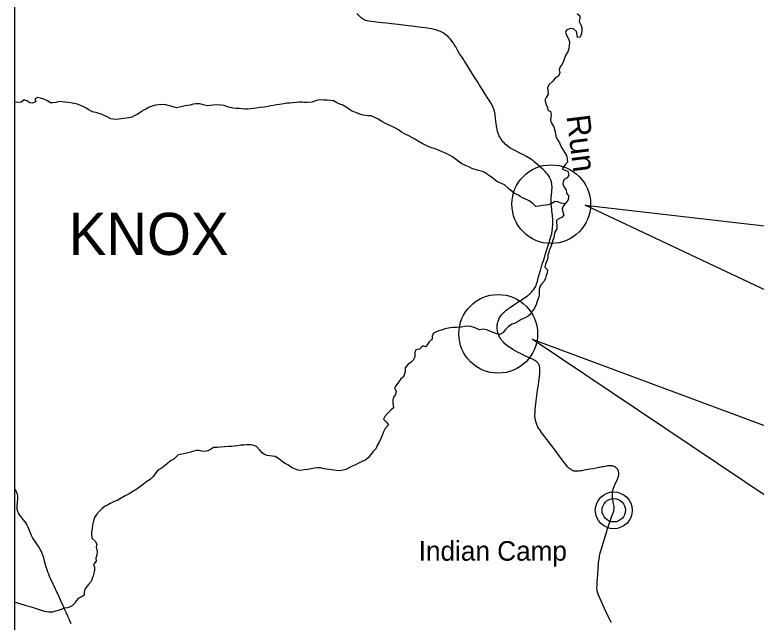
# Model space of a CAD drawing. Extents: x -29.6 to 34, y 0 to 22.
# Drawn here: x -29.583 to -26.775, y 7.101 to 9.402 of the extents above; entities that cross this region are included whole.
import ezdxf

# ---------------------------------------------------------------- set-up
doc = ezdxf.new("R2010")
doc.units = 0
for name, color, linetype in [('BR_P_Gen_Text', 7, 'Continuous'), ('Default', 7, 'Continuous'), ('GM_X_Minor_River', 7, 'Continuous'), ('GM_X_Minor_River_Text', 7, 'Continuous'), ('GM_X_State_Route', 7, 'Continuous'), ('GM_X_Township_Text', 7, 'Continuous'), ('GM_X_Unincorporated', 7, 'Continuous'), ('GM_X_Unincorporated_Location', 7, 'Continuous'), ('GM_X_Unincorporated_Text', 7, 'Continuous'), ('SH_Text', 7, 'Continuous')]:
    doc.layers.add(name, color=color, linetype=linetype)

msp = doc.modelspace()

# ---------------------------------------------------------------- linework, layer by layer
at = {"layer": 'BR_P_Gen_Text'}
for points in [[(-26.5791, 8.5837), (-26.5791, 8.2835), (-27.4233, 8.6813)], [(-26.6185, 7.7998), (-26.6185, 7.4995), (-27.6231, 8.1727)]]:
    msp.add_lwpolyline(points, close=True, dxfattribs=at)
at = {"layer": 'Default'}
for centre in [(-27.5513, 8.6845), (-27.7521, 8.1933)]:
    msp.add_circle(centre, 0.149, dxfattribs=at)
at = {"layer": 'GM_X_Minor_River'}
for points in [[(-27.4532, 9.4073), (-27.4428, 9.3986), (-27.4435, 9.3886), (-27.4448, 9.3769), (-27.4393, 9.3638), (-27.4353, 9.3539), (-27.4349, 9.3404), (-27.4376, 9.3268), (-27.4417, 9.3172), (-27.4513, 9.3157), (-27.4528, 9.3249), (-27.4554, 9.3391), (-27.4672, 9.3486), (-27.4796, 9.3495), (-27.4934, 9.3441), (-27.4976, 9.3344), (-27.4936, 9.3249), (-27.4853, 9.3104), (-27.482, 9.299), (-27.483, 9.2848), (-27.4846, 9.2742), (-27.4884, 9.262), (-27.4958, 9.2499), (-27.5006, 9.2381), (-27.5044, 9.2264), (-27.51, 9.2149), (-27.517, 9.2042), (-27.5218, 9.1931), (-27.5186, 9.1839), (-27.5241, 9.17), (-27.5358, 9.1621), (-27.5452, 9.151), (-27.5597, 9.1384), (-27.5659, 9.1263), (-27.5637, 9.1146), (-27.5625, 9.1011), (-27.5699, 9.0886), (-27.5754, 9.0779), (-27.5703, 9.0623), (-27.566, 9.0513), (-27.5637, 9.041), (-27.5541, 9.0361), (-27.5512, 9.0255), (-27.5532, 9.0123), (-27.5541, 9.001), (-27.5502, 8.9914), (-27.5415, 8.978), (-27.5371, 8.9635), (-27.5356, 8.9511), (-27.5323, 8.9369), (-27.5265, 8.9273), (-27.5197, 8.9164), (-27.5124, 8.8994), (-27.5056, 8.8885), (-27.4991, 8.8789), (-27.494, 8.8687), (-27.4911, 8.8563), (-27.4899, 8.8438), (-27.4997, 8.8317), (-27.5099, 8.8188), (-27.5003, 8.8139), (-27.4889, 8.809), (-27.4845, 8.7942), (-27.4915, 8.7848), (-27.501, 8.7798), (-27.5066, 8.7701), (-27.5069, 8.7609), (-27.5018, 8.7485), (-27.4953, 8.7393), (-27.4938, 8.7262), (-27.4862, 8.7167), (-27.4862, 8.7074), (-27.4879, 8.6985), (-27.4977, 8.6881), (-27.5075, 8.6745), (-27.5103, 8.6653), (-27.5077, 8.6543), (-27.5033, 8.644), (-27.5096, 8.6347), (-27.5227, 8.6289), (-27.5319, 8.6242), (-27.5318, 8.6153), (-27.5296, 8.6054), (-27.5298, 8.5912), (-27.5371, 8.5783), (-27.5406, 8.5669), (-27.5415, 8.5573), (-27.5457, 8.548), (-27.5495, 8.5342), (-27.5529, 8.5235)], [(-28.7119, 9.0443), (-28.7236, 9.046), (-28.7339, 9.0466), (-28.7446, 9.0469), (-28.7559, 9.0482), (-28.7694, 9.0512), (-28.7819, 9.0547), (-28.7908, 9.0581), (-28.8032, 9.0598), (-28.8195, 9.0614), (-28.832, 9.0602), (-28.8433, 9.0587), (-28.8529, 9.0575), (-28.8649, 9.0602), (-28.8738, 9.0626), (-28.8834, 9.0643), (-28.8976, 9.0642), (-28.9072, 9.063), (-28.9192, 9.0593), (-28.9291, 9.0581), (-28.9384, 9.057), (-28.9497, 9.0551), (-28.9592, 9.0522), (-28.9709, 9.0496), (-28.9798, 9.0516), (-28.9919, 9.0554), (-29.0026, 9.0588), (-29.0118, 9.0605), (-29.0253, 9.0618), (-29.0384, 9.0609), (-29.0508, 9.059), (-29.0625, 9.0564), (-29.0742, 9.0517), (-29.0869, 9.0445), (-29.0968, 9.0394), (-29.1084, 9.0318), (-29.1179, 9.026), (-29.1307, 9.0195), (-29.1398, 9.0144), (-29.1515, 9.0115), (-29.1799, 9.0076), (-29.1894, 9.0061), (-29.2008, 9.0053), (-29.2111, 9.0062), (-29.2199, 9.0083), (-29.2338, 9.0149), (-29.2449, 9.0201), (-29.2559, 9.025), (-29.2652, 9.0284), (-29.2755, 9.0312), (-29.2844, 9.0336), (-29.2936, 9.0374), (-29.3026, 9.0419), (-29.3133, 9.0478), (-29.325, 9.0541), (-29.3339, 9.0586), (-29.3457, 9.0631), (-29.3592, 9.0662), (-29.3723, 9.0685), (-29.3816, 9.0699), (-29.3933, 9.0715), (-29.4057, 9.0725), (-29.4149, 9.0731), (-29.4273, 9.0698), (-29.4387, 9.0679), (-29.4475, 9.0688), (-29.4618, 9.0769), (-29.4736, 9.0817), (-29.4857, 9.0859), (-29.497, 9.0882), (-29.5069, 9.0832), (-29.5043, 9.0732), (-29.516, 9.0671), (-29.527, 9.068), (-29.5384, 9.0757), (-29.548, 9.0802), (-29.5593, 9.0713), (-29.5721, 9.0701), (-29.5827, 9.071), (-29.5833, 9.0715)], [(-27.4996, 8.6855), (-27.5066, 8.6873), (-27.5154, 8.6883), (-27.5268, 8.6928), (-27.5368, 8.6942), (-27.5516, 8.6862), (-27.5629, 8.6818), (-27.5732, 8.6807), (-27.5849, 8.6791), (-27.5969, 8.6772), (-27.61, 8.6753), (-27.6219, 8.6887), (-27.6354, 8.6971), (-27.6508, 8.7044), (-27.6597, 8.709), (-27.6686, 8.7142), (-27.6775, 8.7198), (-27.6903, 8.7254), (-27.6996, 8.7331), (-27.7136, 8.744), (-27.7282, 8.7577), (-27.7393, 8.7632), (-27.7489, 8.7667), (-27.7578, 8.7709), (-27.7725, 8.7832), (-27.7814, 8.7898), (-27.796, 8.7996), (-27.8057, 8.8056), (-27.8153, 8.8098), (-27.8263, 8.8125), (-27.8395, 8.8159), (-27.8491, 8.8187), (-27.864, 8.8256), (-27.8765, 8.8315), (-27.8893, 8.8371), (-27.8993, 8.8434), (-27.9101, 8.8522), (-27.9251, 8.8638), (-27.9397, 8.8718), (-27.9515, 8.8781), (-27.9639, 8.8833), (-27.9782, 8.8892), (-27.9945, 8.8954), (-28.0045, 8.8985), (-28.0134, 8.9023), (-28.0227, 8.9058), (-28.0398, 8.9142), (-28.0548, 8.9229), (-28.0683, 8.9313), (-28.0911, 8.9439), (-28.105, 8.9501), (-28.1179, 8.9571), (-28.1304, 8.9659), (-28.1407, 8.9722), (-28.1518, 8.9774), (-28.165, 8.9836), (-28.1785, 8.9899), (-28.1931, 8.9983), (-28.2074, 9.0063), (-28.2216, 9.0136), (-28.233, 9.0192), (-28.2455, 9.0195), (-28.2639, 9.0214), (-28.2764, 9.0255), (-28.2853, 9.0287), (-28.2988, 9.0342), (-28.3084, 9.0387), (-28.3195, 9.0457), (-28.3284, 9.052), (-28.3406, 9.059), (-28.3523, 9.0635), (-28.363, 9.0688), (-28.3755, 9.0757), (-28.3879, 9.0774), (-28.4003, 9.078), (-28.4135, 9.0782), (-28.4227, 9.0792), (-28.4351, 9.0783), (-28.4475, 9.0747), (-28.4574, 9.0714), (-28.4755, 9.0694), (-28.4854, 9.0697), (-28.495, 9.0706), (-28.506, 9.0709), (-28.5156, 9.0697), (-28.5297, 9.0678), (-28.5418, 9.0677), (-28.5514, 9.0669), (-28.5648, 9.065), (-28.5801, 9.062), (-28.5921, 9.0605), (-28.6031, 9.0586), (-28.613, 9.0567), (-28.6233, 9.0545), (-28.6378, 9.0525), (-28.6545, 9.0506), (-28.6686, 9.0483), (-28.6786, 9.0468), (-28.6892, 9.0456), (-28.7023, 9.0444), (-28.7119, 9.0443)], [(-27.5529, 8.5235), (-27.5582, 8.5124), (-27.5609, 8.5031), (-27.5637, 8.4917), (-27.5646, 8.48), (-27.5677, 8.4697), (-27.5733, 8.4579), (-27.5753, 8.4465), (-27.5649, 8.4352), (-27.5669, 8.4238), (-27.5704, 8.4149), (-27.5731, 8.4046), (-27.5784, 8.3935), (-27.5885, 8.3813), (-27.5945, 8.3721), (-27.5965, 8.3617), (-27.5964, 8.3497), (-27.5974, 8.3404), (-27.5998, 8.3294), (-27.6053, 8.3137), (-27.6088, 8.3044), (-27.6147, 8.2905), (-27.6224, 8.2801), (-27.629, 8.2694), (-27.6382, 8.2604), (-27.6502, 8.2546), (-27.6657, 8.2481), (-27.6766, 8.2405), (-27.6883, 8.2336), (-27.6993, 8.2296), (-27.713, 8.2217), (-27.7246, 8.2095), (-27.7341, 8.1966), (-27.7461, 8.1915), (-27.7568, 8.1939), (-27.7674, 8.197), (-27.7774, 8.2011), (-27.7867, 8.2053), (-27.7963, 8.2084), (-27.808, 8.2112), (-27.8229, 8.2082), (-27.8375, 8.2148), (-27.8464, 8.2186), (-27.8564, 8.2217), (-27.8702, 8.2223), (-27.8801, 8.2208), (-27.8915, 8.2182), (-27.9103, 8.218), (-27.923, 8.2171), (-27.934, 8.2156), (-27.9471, 8.213), (-27.9563, 8.2108), (-27.9669, 8.2078), (-27.9768, 8.2045), (-27.9864, 8.2009), (-27.997, 8.1962), (-28.0022, 8.1847), (-28.0021, 8.173), (-28.0137, 8.1633), (-28.0259, 8.144), (-28.0373, 8.1482), (-28.0507, 8.1356), (-28.0638, 8.1323), (-28.0676, 8.1226), (-28.0682, 8.1066), (-28.0748, 8.0938), (-28.0836, 8.0848), (-28.0938, 8.0783), (-28.104, 8.0651), (-28.105, 8.0551), (-28.1059, 8.0459), (-28.1111, 8.0309), (-28.1206, 8.0226), (-28.1301, 8.0097), (-28.1399, 7.9965), (-28.1451, 7.9872), (-28.1386, 7.9766), (-28.1417, 7.9641), (-28.1484, 7.9541), (-28.1515, 7.942), (-28.1517, 7.9321), (-28.1502, 7.9228), (-28.1487, 7.9129), (-28.1589, 7.9039), (-28.1719, 7.8921), (-28.1818, 7.8799), (-28.1866, 7.8706), (-28.1752, 7.8583), (-28.1676, 7.8491), (-28.1803, 7.8344), (-28.1862, 7.8223), (-28.1903, 7.8116), (-28.1956, 7.7998), (-28.2036, 7.7827), (-28.2102, 7.7698), (-28.2157, 7.7573), (-28.2256, 7.748), (-28.2351, 7.7365), (-28.2438, 7.7251), (-28.2533, 7.7165), (-28.2671, 7.7103)], [(-28.2671, 7.7103), (-28.2767, 7.7063), (-28.2957, 7.6965), (-28.3081, 7.6903), (-28.319, 7.6842), (-28.3289, 7.6795), (-28.3399, 7.6765), (-28.3523, 7.6743), (-28.3654, 7.6752), (-28.3747, 7.6765), (-28.3835, 7.6779), (-28.3924, 7.6792), (-28.4024, 7.6802), (-28.4116, 7.6822), (-28.4251, 7.6856), (-28.4351, 7.6862), (-28.4478, 7.6843), (-28.4602, 7.6821), (-28.473, 7.6795), (-28.4871, 7.6779), (-28.501, 7.6763), (-28.5112, 7.6769), (-28.5234, 7.6822), (-28.5348, 7.6874), (-28.5465, 7.6958), (-28.5587, 7.7028), (-28.5687, 7.7091), (-28.5847, 7.7217), (-28.5969, 7.7283), (-28.6079, 7.7303), (-28.6178, 7.731), (-28.6274, 7.733), (-28.6377, 7.7364), (-28.6467, 7.7428), (-28.6553, 7.7533), (-28.6682, 7.7663), (-28.6778, 7.7702), (-28.6885, 7.7725), (-28.7048, 7.7727), (-28.7151, 7.7719), (-28.7278, 7.7711), (-28.7402, 7.7692), (-28.7519, 7.7673), (-28.7611, 7.7665), (-28.7739, 7.766), (-28.7888, 7.7651), (-28.8058, 7.7639), (-28.8168, 7.7631), (-28.8306, 7.7626), (-28.8416, 7.7554), (-28.8522, 7.7499), (-28.8628, 7.7473), (-28.8763, 7.7493), (-28.8862, 7.7517), (-28.8954, 7.7509), (-28.9054, 7.7487), (-28.9163, 7.7454), (-28.9312, 7.7417), (-28.9429, 7.7394), (-28.9563, 7.7361), (-28.9645, 7.7348)], [(-28.9645, 7.7348), (-28.9705, 7.7292), (-28.981, 7.7184), (-28.9905, 7.7134), (-29.0032, 7.7036), (-29.0131, 7.6954), (-29.025, 7.6864), (-29.036, 7.6799), (-29.0451, 7.6719), (-29.0518, 7.663), (-29.0602, 7.6515), (-29.0711, 7.6418), (-29.0831, 7.6335), (-29.0958, 7.6238), (-29.1215, 7.6044), (-29.1356, 7.5957), (-29.1497, 7.5874), (-29.1649, 7.5794), (-29.1801, 7.5707), (-29.1928, 7.5638), (-29.209, 7.5573), (-29.2221, 7.5508), (-29.232, 7.545), (-29.2412, 7.5403), (-29.2528, 7.532), (-29.264, 7.5208), (-29.2742, 7.5087), (-29.2809, 7.4979), (-29.2857, 7.4847), (-29.2891, 7.4698), (-29.2907, 7.4548), (-29.2924, 7.4413), (-29.2927, 7.4321), (-29.2901, 7.4186), (-29.279, 7.4081), (-29.2732, 7.3964), (-29.2752, 7.3857), (-29.2711, 7.3687), (-29.2732, 7.3562), (-29.277, 7.3441), (-29.2747, 7.3328), (-29.2852, 7.3195), (-29.2812, 7.3092), (-29.2811, 7.2986), (-29.2842, 7.2868), (-29.2863, 7.2772), (-29.2908, 7.2669), (-29.2946, 7.2555), (-29.3044, 7.2436), (-29.3184, 7.2268), (-29.3201, 7.215), (-29.3207, 7.203), (-29.332, 7.1964), (-29.3426, 7.1924), (-29.3503, 7.182), (-29.3555, 7.1731), (-29.3643, 7.1638), (-29.3742, 7.1591), (-29.3838, 7.1558), (-29.3965, 7.1539), (-29.4075, 7.1498), (-29.4191, 7.1455), (-29.4298, 7.1425), (-29.4407, 7.1392), (-29.4563, 7.1391), (-29.4706, 7.1421), (-29.494, 7.1497), (-29.5093, 7.1538), (-29.5253, 7.1593), (-29.5399, 7.1627), (-29.5517, 7.1665), (-29.5638, 7.1703), (-29.5762, 7.1741), (-29.5833, 7.1754)]]:
    msp.add_lwpolyline(points, dxfattribs=at)
at = {"layer": 'GM_X_State_Route'}
for points in [[(-27.7557, 8.2285), (-27.7554, 8.2306), (-27.7547, 8.2339), (-27.754, 8.2366), (-27.7526, 8.2409), (-27.7503, 8.2473), (-27.7492, 8.25), (-27.747, 8.2544), (-27.7458, 8.2566), (-27.7433, 8.2604), (-27.7419, 8.2622), (-27.7382, 8.2671), (-27.7348, 8.2708), (-27.7333, 8.2724), (-27.7295, 8.276), (-27.7237, 8.2812), (-27.7166, 8.2867), (-27.706, 8.2939), (-27.6929, 8.3027), (-27.6775, 8.3129), (-27.665, 8.3213), (-27.6549, 8.3282), (-27.643, 8.3366), (-27.6375, 8.3408), (-27.6335, 8.3441), (-27.6296, 8.3476), (-27.6263, 8.3507), (-27.6243, 8.3527), (-27.6216, 8.3557), (-27.6184, 8.3598), (-27.6156, 8.3636), (-27.6133, 8.3673), (-27.6111, 8.3716), (-27.6088, 8.3768), (-27.6067, 8.3825), (-27.6044, 8.3897), (-27.6022, 8.3974), (-27.5989, 8.4096), (-27.5968, 8.4176), (-27.5949, 8.4245), (-27.594, 8.4276), (-27.5924, 8.4328), (-27.5878, 8.4481), (-27.584, 8.4605), (-27.5811, 8.4696), (-27.5782, 8.4791), (-27.576, 8.4862), (-27.5738, 8.4931), (-27.5686, 8.509), (-27.5623, 8.5281), (-27.5586, 8.5397), (-27.5548, 8.5527), (-27.5511, 8.566), (-27.5496, 8.5727), (-27.5485, 8.5776), (-27.5481, 8.5802), (-27.5471, 8.5867), (-27.5467, 8.5903), (-27.546, 8.5974), (-27.5456, 8.6044), (-27.5454, 8.612), (-27.5455, 8.6182), (-27.5455, 8.6237), (-27.5457, 8.6298), (-27.5461, 8.6356), (-27.5465, 8.64), (-27.547, 8.6438), (-27.5473, 8.6473), (-27.5477, 8.6507), (-27.5487, 8.6591), (-27.5494, 8.6645), (-27.5506, 8.6762), (-27.5513, 8.6845), (-27.5516, 8.6921), (-27.5517, 8.702), (-27.5511, 8.712), (-27.5495, 8.7298), (-27.5486, 8.7385), (-27.5483, 8.7451), (-27.5482, 8.7512), (-27.5484, 8.7541), (-27.5493, 8.7621), (-27.55, 8.766), (-27.5507, 8.7689), (-27.552, 8.7734), (-27.5528, 8.7757), (-27.5538, 8.7784), (-27.5561, 8.7834), (-27.5584, 8.7878), (-27.562, 8.7934), (-27.5651, 8.7978), (-27.5687, 8.8023), (-27.5743, 8.8081), (-27.5809, 8.8145), (-27.5882, 8.8212), (-27.5931, 8.8255), (-27.6037, 8.8349), (-27.6143, 8.8439), (-27.62, 8.8486), (-27.6264, 8.8535), (-27.6323, 8.8575), (-27.6387, 8.8614), (-27.6449, 8.8647), (-27.6567, 8.8709), (-27.6705, 8.878), (-27.6813, 8.8836), (-27.6946, 8.8905), (-27.7027, 8.8949), (-27.7082, 8.8984), (-27.7134, 8.902), (-27.718, 8.9056), (-27.7252, 8.9121), (-27.7297, 8.9163), (-27.7342, 8.9212), (-27.7366, 8.9242), (-27.7385, 8.9267), (-27.7412, 8.9305), (-27.743, 8.9331), (-27.7465, 8.939), (-27.7485, 8.943), (-27.75, 8.9461), (-27.7515, 8.9497), (-27.7525, 8.9523), (-27.7531, 8.9544), (-27.754, 8.9576), (-27.7546, 8.9601), (-27.7565, 8.9692), (-27.7585, 8.9795), (-27.7589, 8.9831), (-27.7608, 8.998), (-27.7624, 9.0133), (-27.7632, 9.0203), (-27.7639, 9.0244), (-27.7652, 9.0307), (-27.7666, 9.0363), (-27.7688, 9.044), (-27.7715, 9.0513), (-27.775, 9.059), (-27.7804, 9.0689), (-27.7862, 9.0785), (-27.7921, 9.0876), (-27.7987, 9.0978), (-27.8051, 9.1079), (-27.8127, 9.1197), (-27.8225, 9.1355), (-27.8299, 9.1473), (-27.844, 9.1699), (-27.8604, 9.1963), (-27.8726, 9.2155), (-27.8773, 9.2229), (-27.8799, 9.2268), (-27.8824, 9.2308), (-27.8905, 9.2429), (-27.8934, 9.2471), (-27.8982, 9.2546), (-27.9066, 9.2682), (-27.9106, 9.2757), (-27.913, 9.28), (-27.9162, 9.2855), (-27.9185, 9.2892), (-27.9208, 9.2929), (-27.9238, 9.2975), (-27.9261, 9.3006), (-27.9296, 9.3051), (-27.934, 9.3106), (-27.9389, 9.3161), (-27.9435, 9.3205), (-27.9489, 9.3251), (-27.9545, 9.3291), (-27.9607, 9.333), (-27.9659, 9.3358), (-27.971, 9.3383), (-27.9737, 9.3394), (-27.9794, 9.3417), (-27.985, 9.3436), (-27.9877, 9.3444), (-27.9942, 9.3462), (-28.0034, 9.3483), (-28.014, 9.3502), (-28.0289, 9.3525), (-28.0426, 9.3542), (-28.0508, 9.3552), (-28.0618, 9.3566), (-28.0797, 9.3586), (-28.0936, 9.3602), (-28.1028, 9.3614), (-28.1312, 9.365), (-28.1566, 9.368), (-28.175, 9.3701), (-28.1915, 9.372), (-28.2029, 9.3731), (-28.2214, 9.375), (-28.2324, 9.3764), (-28.2422, 9.3781), (-28.248, 9.3793), (-28.2519, 9.3803), (-28.2535, 9.3808), (-28.2569, 9.3821), (-28.2584, 9.3827), (-28.2617, 9.3843), (-28.263, 9.385), (-28.2667, 9.3871), (-28.27, 9.3895), (-28.2736, 9.3925), (-28.2781, 9.3968), (-28.2821, 9.4012), (-28.2864, 9.4068)], [(-27.3227, 7.0984), (-27.3268, 7.1061), (-27.3329, 7.1181), (-27.3414, 7.136), (-27.3489, 7.1524), (-27.3552, 7.1668), (-27.3604, 7.1785), (-27.3642, 7.187), (-27.3691, 7.1982), (-27.373, 7.2073), (-27.3747, 7.2115), (-27.3757, 7.2144), (-27.377, 7.2191), (-27.3773, 7.2217), (-27.3776, 7.2239), (-27.3779, 7.2316), (-27.3774, 7.2413), (-27.3767, 7.253), (-27.3757, 7.2687), (-27.375, 7.2791), (-27.3746, 7.2855), (-27.3736, 7.303), (-27.373, 7.3123), (-27.3728, 7.3163), (-27.3716, 7.3268), (-27.3701, 7.3401), (-27.3682, 7.3516), (-27.3668, 7.3594), (-27.3646, 7.3681), (-27.3589, 7.3872), (-27.3446, 7.4333), (-27.341, 7.4451), (-27.3375, 7.4556), (-27.3327, 7.4701), (-27.3253, 7.4916), (-27.3224, 7.4998), (-27.3165, 7.5156), (-27.3146, 7.5215), (-27.3136, 7.526), (-27.313, 7.5299), (-27.3128, 7.5333), (-27.313, 7.5356), (-27.3134, 7.5392), (-27.3153, 7.5493), (-27.318, 7.5648), (-27.3187, 7.57), (-27.3193, 7.577), (-27.3196, 7.5841), (-27.3193, 7.5891), (-27.3191, 7.5914), (-27.3186, 7.595), (-27.3174, 7.6016), (-27.3152, 7.6086), (-27.3125, 7.6156), (-27.3086, 7.625), (-27.3008, 7.6414), (-27.2985, 7.647), (-27.2972, 7.6508), (-27.2967, 7.6525), (-27.2958, 7.656), (-27.2955, 7.6577), (-27.2953, 7.6603), (-27.2952, 7.662), (-27.2953, 7.6659), (-27.2956, 7.6687), (-27.296, 7.6706), (-27.2964, 7.6721), (-27.297, 7.6741), (-27.2983, 7.6768), (-27.2999, 7.6797), (-27.3006, 7.681), (-27.3018, 7.6827), (-27.3034, 7.6845), (-27.3052, 7.6861), (-27.307, 7.6875), (-27.308, 7.6882), (-27.3094, 7.6891), (-27.3107, 7.6898), (-27.3135, 7.6911), (-27.3167, 7.6921), (-27.3207, 7.6931), (-27.3246, 7.6935), (-27.3291, 7.6936), (-27.3331, 7.6935), (-27.3376, 7.6929), (-27.3416, 7.6922), (-27.3472, 7.6913), (-27.3528, 7.6902), (-27.3558, 7.6896), (-27.3593, 7.689), (-27.3626, 7.6884), (-27.3667, 7.6876), (-27.3713, 7.6867), (-27.3755, 7.6859), (-27.3809, 7.6848), (-27.3928, 7.6825), (-27.4049, 7.6803), (-27.4113, 7.6791), (-27.419, 7.6777), (-27.4267, 7.6764), (-27.4348, 7.675), (-27.4403, 7.6742), (-27.4453, 7.6736), (-27.4515, 7.6731), (-27.4554, 7.673), (-27.4596, 7.6731), (-27.464, 7.6737), (-27.4669, 7.6744), (-27.4682, 7.6747), (-27.4693, 7.675), (-27.4713, 7.6758), (-27.4732, 7.6767), (-27.4761, 7.6782), (-27.4776, 7.6791), (-27.4813, 7.6817), (-27.4842, 7.6841), (-27.4856, 7.6855), (-27.4892, 7.6893), (-27.4962, 7.6979), (-27.5013, 7.7047), (-27.5066, 7.7116), (-27.5095, 7.7156), (-27.5123, 7.7193), (-27.519, 7.7281), (-27.533, 7.7472), (-27.5418, 7.7587), (-27.5546, 7.7758), (-27.5665, 7.7914), (-27.579, 7.808), (-27.5878, 7.8198), (-27.5922, 7.8259), (-27.5958, 7.8311), (-27.5973, 7.8334), (-27.6014, 7.8403), (-27.6023, 7.842), (-27.6032, 7.8438), (-27.604, 7.8454), (-27.6051, 7.8478), (-27.6059, 7.8498), (-27.6075, 7.8538), (-27.6086, 7.8571), (-27.6094, 7.8598), (-27.6102, 7.8626), (-27.611, 7.8662), (-27.6117, 7.8696), (-27.6123, 7.8746), (-27.6128, 7.8792), (-27.613, 7.882), (-27.6131, 7.8858), (-27.6126, 7.8941), (-27.6122, 7.8998), (-27.6116, 7.9073), (-27.6078, 7.9401), (-27.6027, 7.9797), (-27.6008, 7.9935), (-27.6, 7.9993), (-27.598, 8.0147), (-27.596, 8.03), (-27.5945, 8.0414), (-27.594, 8.0509), (-27.5939, 8.0536), (-27.5941, 8.0588), (-27.5945, 8.0638), (-27.5949, 8.0667), (-27.5956, 8.0702), (-27.5963, 8.0727), (-27.597, 8.0749), (-27.5979, 8.0771), (-27.5989, 8.0793), (-27.6003, 8.0815), (-27.6025, 8.0841), (-27.6045, 8.0864), (-27.6059, 8.0876), (-27.6072, 8.0887), (-27.6095, 8.0902), (-27.6129, 8.0924), (-27.615, 8.0936), (-27.6193, 8.0956), (-27.633, 8.102), (-27.6491, 8.1092), (-27.6657, 8.1175), (-27.6786, 8.124), (-27.6835, 8.1265), (-27.6858, 8.1278), (-27.6973, 8.1343), (-27.7023, 8.1374), (-27.7086, 8.1416), (-27.7138, 8.1454), (-27.7202, 8.1505), (-27.7264, 8.1558), (-27.7311, 8.1603), (-27.7346, 8.1642), (-27.738, 8.1682), (-27.7393, 8.1699), (-27.7412, 8.1724), (-27.7426, 8.1744), (-27.7452, 8.1783), (-27.7467, 8.1809), (-27.7484, 8.1841), (-27.7503, 8.1883), (-27.7514, 8.1912), (-27.7521, 8.1933), (-27.7535, 8.1977), (-27.754, 8.1997), (-27.7547, 8.2026), (-27.7554, 8.2062), (-27.756, 8.2116), (-27.7563, 8.2178), (-27.7562, 8.2233), (-27.7559, 8.2263), (-27.7557, 8.2285)], [(-29.3696, 7.0955), (-29.3735, 7.104), (-29.376, 7.11), (-29.3806, 7.12), (-29.3827, 7.1248), (-29.3853, 7.1303), (-29.3871, 7.1342), (-29.3875, 7.1353), (-29.3909, 7.1426), (-29.3935, 7.1483), (-29.3959, 7.1536), (-29.3981, 7.1583), (-29.4005, 7.1636), (-29.4085, 7.1817), (-29.4169, 7.2003), (-29.4289, 7.2268), (-29.4338, 7.2374), (-29.4377, 7.2452), (-29.4479, 7.2672), (-29.4513, 7.2745), (-29.4549, 7.2828), (-29.458, 7.2907), (-29.461, 7.2989), (-29.4642, 7.3093), (-29.4705, 7.3324), (-29.4738, 7.3444), (-29.4764, 7.3526), (-29.4794, 7.3608), (-29.4828, 7.3685), (-29.487, 7.3767), (-29.4915, 7.385), (-29.496, 7.3922), (-29.5067, 7.4071), (-29.512, 7.4151), (-29.5162, 7.4225), (-29.5198, 7.4295), (-29.5226, 7.4354), (-29.5252, 7.4417), (-29.5299, 7.4542), (-29.5338, 7.4635), (-29.5378, 7.4713), (-29.5418, 7.4777), (-29.5447, 7.4814), (-29.5517, 7.4898), (-29.5598, 7.5001), (-29.5657, 7.5077), (-29.5681, 7.5117), (-29.5698, 7.5151), (-29.572, 7.5206), (-29.5732, 7.5247), (-29.5743, 7.531), (-29.5749, 7.5372), (-29.5745, 7.5442), (-29.5736, 7.5504), (-29.5726, 7.558), (-29.5717, 7.5661), (-29.5714, 7.5707), (-29.5716, 7.5748), (-29.5721, 7.5801), (-29.573, 7.5844), (-29.5742, 7.5888), (-29.5761, 7.5936), (-29.5782, 7.5975), (-29.5823, 7.6038), (-29.5833, 7.605)]]:
    msp.add_lwpolyline(points, dxfattribs=at)
at = {"layer": 'GM_X_Unincorporated'}
for radius in [0.0698, 0.0442]:
    msp.add_circle((-27.3144, 7.5249), radius, dxfattribs=at)
at = {"layer": 'GM_X_Unincorporated_Location'}
msp.add_line((-27.3144, 7.5249), (-27.3144, 7.5249), dxfattribs=at)
at = {"layer": 'SH_Text'}
msp.add_lwpolyline([(-29.5833, 13.2079), (-10.7478, 13.2079), (-10.7478, 1.0528), (-29.5833, 1.0528)], close=True, dxfattribs=at)

# ---------------------------------------------------------------- texts
at = {"layer": 'GM_X_Minor_River_Text'}
msp.add_text('Run', height=0.08877, rotation=277.0886, dxfattribs=at).set_placement((-27.4938, 9.0184))
at = {"layer": 'GM_X_Township_Text'}
msp.add_text('KNOX', height=0.1598, rotation=0, dxfattribs=at).set_placement((-29.3792, 8.4921))
at = {"layer": 'GM_X_Unincorporated_Text'}
msp.add_text('Indian Camp', height=0.074041, rotation=0, dxfattribs=at).set_placement((-28.0532, 7.3341))

doc.saveas('drawing.dxf')
